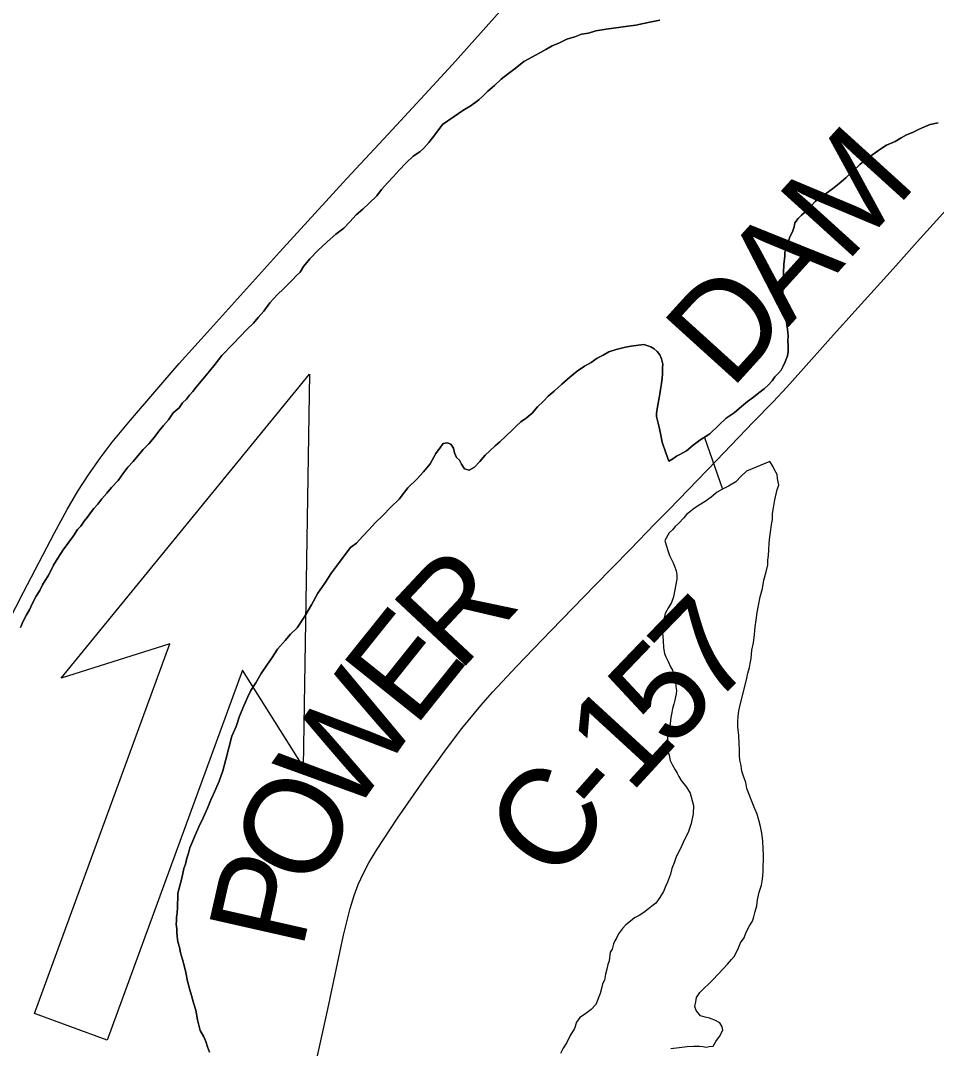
# Model space of a CAD drawing. Extents: x -483 to 680, y 0 to 440.
# Drawn here: x 125.22 to 151.99, y 130.81 to 160.88 of the extents above; entities that cross this region are included whole.
import ezdxf

# ---------------------------------------------------------------- set-up
doc = ezdxf.new("R2010")
doc.units = 0
for name, color, linetype in [('GM_X_County_Road', 7, 'Continuous'), ('GM_X_County_Road_Text', 7, 'Continuous'), ('GM_X_Major_River', 7, 'Continuous'), ('GM_X_Minor_Lake', 7, 'Continuous'), ('GM_X_Minor_River', 7, 'Continuous'), ('GM_X_State_Route', 7, 'Continuous'), ('PM_P_Cells', 7, 'Continuous')]:
    doc.layers.add(name, color=color, linetype=linetype)

msp = doc.modelspace()

# ---------------------------------------------------------------- linework, layer by layer
at = {"layer": 'GM_X_County_Road'}
msp.add_lwpolyline([(133.774, 130.022), (134.2, 131.965), (134.667, 134.122), (134.859, 134.904), (134.973, 135.289), (135.091, 135.606), (135.242, 135.943), (135.401, 136.243), (135.625, 136.613), (136.243, 137.544), (137.021, 138.669), (137.674, 139.576), (138.122, 140.17), (138.674, 140.841), (139.02, 141.238), (139.718, 141.988), (140.735, 143.036), (142.012, 144.352), (143.051, 145.421), (143.762, 146.161), (144.177, 146.579), (145.561, 148.007), (146.64, 149.127), (147.217, 149.729), (147.619, 150.154), (148.032, 150.613), (148.897, 151.586), (149.707, 152.485), (150.726, 153.615), (151.425, 154.404), (152.467, 155.545)], dxfattribs=at)
at = {"layer": 'GM_X_Major_River'}
for points in [[(143.913, 160.893), (143.664, 160.844), (143.434, 160.795), (143.204, 160.746), (142.975, 160.715), (142.764, 160.684), (142.554, 160.653), (142.343, 160.622), (142.037, 160.575), (141.825, 160.506), (141.615, 160.475), (141.422, 160.405), (141.192, 160.337), (140.979, 160.23), (140.766, 160.142), (140.573, 160.034), (140.417, 159.944), (139.933, 159.675), (139.679, 159.474), (139.484, 159.329), (139.269, 159.165), (139.073, 158.981), (138.877, 158.816), (138.739, 158.669), (138.621, 158.558), (138.504, 158.467), (138.368, 158.376), (138.154, 158.25), (137.901, 158.069), (137.551, 157.833), (137.332, 157.536), (137.153, 157.314), (137.015, 157.147), (136.897, 157.037), (136.702, 156.91), (136.486, 156.708), (136.289, 156.505), (136.112, 156.302), (135.954, 156.136), (135.776, 155.933), (135.637, 155.747), (135.401, 155.527), (135.225, 155.361), (135.029, 155.197), (134.851, 154.994), (134.674, 154.809), (134.439, 154.627), (134.185, 154.407), (133.91, 154.15), (133.674, 153.91), (133.495, 153.688)], [(133.495, 153.688), (133.674, 153.91), (133.91, 154.15), (134.185, 154.407), (134.439, 154.627), (134.674, 154.809), (134.851, 154.994), (135.029, 155.197), (135.225, 155.361), (135.401, 155.527), (135.637, 155.747), (135.776, 155.933), (135.954, 156.136), (136.112, 156.302), (136.289, 156.505), (136.486, 156.708), (136.702, 156.91), (136.897, 157.037), (137.015, 157.147), (137.153, 157.314), (137.332, 157.536), (137.551, 157.833), (137.901, 158.069), (138.154, 158.25), (138.368, 158.376), (138.504, 158.467), (138.621, 158.558), (138.739, 158.669), (138.877, 158.816), (139.073, 158.981), (139.269, 159.165), (139.484, 159.329), (139.679, 159.474), (139.933, 159.675), (140.417, 159.944), (140.573, 160.034), (140.766, 160.142), (140.979, 160.23), (141.192, 160.337), (141.422, 160.405), (141.615, 160.475), (141.825, 160.506), (142.037, 160.575), (142.343, 160.622), (142.554, 160.653), (142.764, 160.684), (142.975, 160.715), (143.204, 160.746), (143.434, 160.795), (143.664, 160.844), (143.913, 160.893)], [(147.076, 150.212), (147.194, 150.341), (147.274, 150.452), (147.372, 150.563), (147.452, 150.656), (147.512, 150.768), (147.574, 150.899), (147.636, 151.068), (147.659, 151.2), (147.664, 151.353), (147.651, 151.524), (147.655, 151.657), (147.642, 151.848), (147.578, 152.23), (147.562, 152.326), (147.547, 152.46), (147.533, 152.593), (147.5, 152.766), (147.507, 152.994), (147.513, 153.165), (147.518, 153.317), (147.523, 153.488), (147.532, 153.754), (147.558, 153.981), (147.562, 154.095), (147.605, 154.246), (147.646, 154.359), (147.709, 154.547), (147.79, 154.696), (147.833, 154.847), (147.856, 154.96), (147.955, 155.09), (148.053, 155.182), (148.191, 155.311), (148.329, 155.458), (148.447, 155.587), (148.623, 155.715), (148.778, 155.824), (148.954, 155.951), (149.15, 156.116), (149.345, 156.28), (149.561, 156.482), (149.758, 156.666), (149.934, 156.813), (150.129, 156.958), (150.343, 157.103), (150.537, 157.23), (150.788, 157.336), (150.963, 157.444), (151.118, 157.534), (151.292, 157.604), (151.466, 157.694), (151.64, 157.764), (151.813, 157.834), (152.043, 157.884)], [(152.043, 157.884), (151.813, 157.834), (151.64, 157.764), (151.466, 157.694), (151.292, 157.604), (151.118, 157.534), (150.963, 157.444), (150.788, 157.336), (150.537, 157.23), (150.343, 157.103), (150.129, 156.958), (149.934, 156.813), (149.758, 156.666), (149.561, 156.482), (149.345, 156.28), (149.15, 156.116), (148.954, 155.951), (148.778, 155.824), (148.623, 155.715), (148.447, 155.587), (148.329, 155.458), (148.191, 155.311), (148.053, 155.182), (147.955, 155.09), (147.856, 154.96), (147.833, 154.847), (147.79, 154.696), (147.709, 154.547), (147.646, 154.359), (147.605, 154.246), (147.562, 154.095), (147.558, 153.981), (147.532, 153.754), (147.523, 153.488), (147.518, 153.317), (147.513, 153.165), (147.507, 152.994), (147.5, 152.766), (147.533, 152.593), (147.547, 152.46), (147.562, 152.326), (147.578, 152.23), (147.642, 151.848), (147.655, 151.657), (147.651, 151.524), (147.664, 151.353), (147.659, 151.2), (147.636, 151.068), (147.574, 150.899), (147.512, 150.768), (147.452, 150.656), (147.372, 150.563), (147.274, 150.452), (147.194, 150.341), (147.076, 150.212)], [(133.495, 153.688), (133.395, 153.52), (133.277, 153.41), (133.178, 153.299), (133.06, 153.189), (132.922, 153.041), (132.726, 152.858), (132.509, 152.618), (132.33, 152.376), (132.172, 152.191), (132.033, 152.025), (131.837, 151.841), (131.64, 151.638), (131.423, 151.417), (131.108, 151.085), (130.909, 150.826), (130.75, 150.622), (130.355, 150.159), (130.255, 150.029), (130.157, 149.919), (130.077, 149.807), (129.959, 149.697), (129.859, 149.548), (129.683, 149.402), (129.543, 149.197), (129.405, 149.031), (129.266, 148.864), (129.127, 148.678), (128.969, 148.493), (128.811, 148.327), (128.653, 148.142), (128.514, 147.976), (128.356, 147.81), (128.217, 147.624), (128.077, 147.42), (127.88, 147.217), (127.742, 147.05), (127.603, 146.884), (127.484, 146.736), (127.366, 146.606), (127.266, 146.477), (127.167, 146.347), (127.087, 146.235), (126.987, 146.086), (126.889, 145.995), (126.769, 145.808), (126.63, 145.623), (126.47, 145.4), (126.31, 145.158), (126.189, 144.953), (126.108, 144.784), (126.027, 144.635), (125.947, 144.504), (125.866, 144.374), (125.785, 144.205), (125.684, 144.037), (125.563, 143.813), (125.481, 143.645), (125.4, 143.495), (125.299, 143.308), (125.217, 143.121)], [(125.217, 143.121), (125.299, 143.308), (125.4, 143.495), (125.481, 143.645), (125.563, 143.813), (125.684, 144.037), (125.785, 144.205), (125.866, 144.374), (125.947, 144.504), (126.027, 144.635), (126.108, 144.784), (126.189, 144.953), (126.31, 145.158), (126.47, 145.4), (126.63, 145.623), (126.769, 145.808), (126.889, 145.995), (126.987, 146.086), (127.087, 146.235), (127.167, 146.347), (127.266, 146.477), (127.366, 146.606), (127.484, 146.736), (127.603, 146.884), (127.742, 147.05), (127.88, 147.217), (128.077, 147.42), (128.217, 147.624), (128.356, 147.81), (128.514, 147.976), (128.653, 148.142), (128.811, 148.327), (128.969, 148.493), (129.127, 148.678), (129.266, 148.864), (129.405, 149.031), (129.543, 149.197), (129.683, 149.402), (129.859, 149.548), (129.959, 149.697), (130.077, 149.807), (130.157, 149.919), (130.255, 150.029), (130.355, 150.159), (130.75, 150.622), (130.909, 150.826), (131.108, 151.085), (131.423, 151.417), (131.64, 151.638), (131.837, 151.841), (132.033, 152.025), (132.172, 152.191), (132.33, 152.376), (132.509, 152.618), (132.726, 152.858), (132.922, 153.041), (133.06, 153.189), (133.178, 153.299), (133.277, 153.41), (133.395, 153.52), (133.495, 153.688)], [(133.113, 142.934), (133.31, 143.118), (133.53, 143.453), (133.731, 143.789), (133.913, 144.125), (134.113, 144.423), (134.313, 144.72), (134.512, 144.999), (134.711, 145.259), (134.87, 145.463), (135.045, 145.59), (135.223, 145.793), (135.401, 145.978), (135.598, 146.199), (135.814, 146.401), (136.05, 146.641), (136.286, 146.88), (136.445, 147.084), (136.545, 147.214), (136.819, 147.471), (136.997, 147.675), (137.195, 147.915), (137.357, 148.214), (137.496, 148.4), (137.576, 148.511), (137.691, 148.527), (137.804, 148.485), (137.876, 148.368), (137.91, 148.234), (137.963, 148.099), (138.056, 148.02), (138.109, 147.904), (138.2, 147.768), (138.332, 147.725), (138.487, 147.815), (138.645, 147.981), (138.803, 148.166), (138.94, 148.295), (139.097, 148.442), (139.234, 148.551), (139.588, 148.901), (139.706, 149.011), (139.843, 149.14), (139.999, 149.249), (140.175, 149.395), (140.333, 149.58), (140.51, 149.745), (140.648, 149.893), (140.824, 150.039), (141.04, 150.241), (141.275, 150.443), (141.49, 150.626), (141.704, 150.771), (141.898, 150.878), (142.074, 151.006), (142.248, 151.095), (142.422, 151.184), (142.634, 151.253), (142.903, 151.321), (143.075, 151.353), (143.286, 151.384), (143.438, 151.398), (143.646, 151.334), (143.739, 151.274), (143.832, 151.195), (143.905, 151.097), (143.958, 150.981), (143.992, 150.828), (143.988, 150.733), (143.985, 150.619), (143.982, 150.524), (143.979, 150.429), (143.954, 150.258), (143.93, 150.088), (143.906, 149.956), (143.884, 149.842), (143.86, 149.691), (143.837, 149.578), (143.812, 149.388), (143.809, 149.293), (143.877, 149.025), (143.926, 148.795), (143.976, 148.546), (144.08, 148.238), (144.167, 147.988), (144.284, 148.06), (144.4, 148.132), (144.497, 148.186), (144.691, 148.294), (144.887, 148.458), (145.082, 148.604), (145.373, 148.785), (145.629, 149.042), (145.845, 149.244), (146.079, 149.408), (146.294, 149.591), (146.47, 149.737), (146.646, 149.865), (146.802, 149.993), (146.958, 150.101), (147.076, 150.212)], [(147.076, 150.212), (146.958, 150.101), (146.802, 149.993), (146.646, 149.865), (146.47, 149.737), (146.294, 149.591), (146.079, 149.408), (145.845, 149.244), (145.629, 149.042), (145.373, 148.785), (145.082, 148.604), (144.887, 148.458), (144.691, 148.294), (144.497, 148.186), (144.4, 148.132), (144.284, 148.06), (144.167, 147.988), (144.08, 148.238), (143.976, 148.546), (143.926, 148.795), (143.877, 149.025), (143.809, 149.293), (143.812, 149.388), (143.837, 149.578), (143.86, 149.691), (143.884, 149.842), (143.906, 149.956), (143.93, 150.088), (143.954, 150.258), (143.979, 150.429), (143.982, 150.524), (143.985, 150.619), (143.988, 150.733), (143.992, 150.828), (143.958, 150.981), (143.905, 151.097), (143.832, 151.195), (143.739, 151.274), (143.646, 151.334), (143.438, 151.398), (143.286, 151.384), (143.075, 151.353), (142.903, 151.321), (142.634, 151.253), (142.422, 151.184), (142.248, 151.095), (142.074, 151.006), (141.898, 150.878), (141.704, 150.771), (141.49, 150.626), (141.275, 150.443), (141.04, 150.241), (140.824, 150.039), (140.648, 149.893), (140.51, 149.745), (140.333, 149.58), (140.175, 149.395), (139.999, 149.249), (139.843, 149.14), (139.706, 149.011), (139.588, 148.901), (139.234, 148.551), (139.097, 148.442), (138.94, 148.295), (138.803, 148.166), (138.645, 147.981), (138.487, 147.815), (138.332, 147.725), (138.2, 147.768), (138.109, 147.904), (138.056, 148.02), (137.963, 148.099), (137.91, 148.234), (137.876, 148.368), (137.804, 148.485), (137.691, 148.527), (137.576, 148.511), (137.496, 148.4), (137.357, 148.214), (137.195, 147.915), (136.997, 147.675), (136.819, 147.471), (136.545, 147.214), (136.445, 147.084), (136.286, 146.88), (136.05, 146.641), (135.814, 146.401), (135.598, 146.199), (135.401, 145.978), (135.223, 145.793), (135.045, 145.59), (134.87, 145.463), (134.711, 145.259), (134.512, 144.999), (134.313, 144.72), (134.113, 144.423), (133.913, 144.125), (133.731, 143.789), (133.53, 143.453), (133.31, 143.118), (133.113, 142.934)], [(130.742, 130.706), (130.689, 130.86), (130.637, 131.014), (130.584, 131.149), (130.476, 131.342), (130.391, 131.649), (130.343, 131.936), (130.274, 132.148), (130.223, 132.359), (130.172, 132.532), (130.104, 132.781), (130.054, 133.03), (130.004, 133.241), (129.952, 133.414), (129.901, 133.606), (129.869, 133.778), (129.817, 133.932), (129.802, 134.085), (129.788, 134.219), (129.791, 134.313), (129.776, 134.447), (129.779, 134.542), (129.783, 134.656), (129.805, 134.77), (129.811, 134.941), (129.814, 135.055), (129.819, 135.188), (129.824, 135.359), (129.933, 135.792), (129.977, 135.981), (129.999, 136.076), (130.042, 136.207), (130.085, 136.377), (130.128, 136.528), (130.171, 136.679), (130.254, 136.885), (130.336, 137.073), (130.438, 137.297), (130.561, 137.56), (130.684, 137.841), (130.787, 138.085), (130.849, 138.235), (130.931, 138.403), (131.033, 138.628), (131.138, 138.929), (131.225, 139.269), (131.312, 139.608), (131.399, 139.948), (131.522, 140.229), (131.627, 140.53), (131.751, 140.83), (131.854, 141.074), (131.956, 141.28), (132.096, 141.503), (132.258, 141.783), (132.418, 142.025), (132.577, 142.248), (132.737, 142.49), (132.955, 142.749), (133.113, 142.934)], [(133.113, 142.934), (132.955, 142.749), (132.737, 142.49), (132.577, 142.248), (132.418, 142.025), (132.258, 141.783), (132.096, 141.503), (131.956, 141.28), (131.854, 141.074), (131.751, 140.83), (131.627, 140.53), (131.522, 140.229), (131.399, 139.948), (131.312, 139.608), (131.225, 139.269), (131.138, 138.929), (131.033, 138.628), (130.931, 138.403), (130.849, 138.235), (130.787, 138.085), (130.684, 137.841), (130.561, 137.56), (130.438, 137.297), (130.336, 137.073), (130.254, 136.885), (130.171, 136.679), (130.128, 136.528), (130.085, 136.377), (130.042, 136.207), (129.999, 136.076), (129.977, 135.981), (129.933, 135.792), (129.824, 135.359), (129.819, 135.188), (129.814, 135.055), (129.811, 134.941), (129.805, 134.77), (129.783, 134.656), (129.779, 134.542), (129.776, 134.447), (129.791, 134.313), (129.788, 134.219), (129.802, 134.085), (129.817, 133.932), (129.869, 133.778), (129.901, 133.606), (129.952, 133.414), (130.004, 133.241), (130.054, 133.03), (130.104, 132.781), (130.172, 132.532), (130.223, 132.359), (130.274, 132.148), (130.343, 131.936), (130.391, 131.649), (130.476, 131.342), (130.584, 131.149), (130.637, 131.014), (130.689, 130.86), (130.742, 130.706)]]:
    msp.add_lwpolyline(points, dxfattribs=at)
at = {"layer": 'GM_X_Minor_Lake'}
for points in [[(147.12, 147.984), (146.444, 147.702), (146.287, 147.555), (146.13, 147.389), (145.916, 147.263), (145.742, 147.174), (145.587, 147.084), (145.411, 146.938), (145.235, 146.81), (145.06, 146.702), (144.924, 146.611), (144.827, 146.538), (144.69, 146.429), (144.611, 146.336), (144.453, 146.17), (144.355, 146.079), (144.276, 145.986), (144.178, 145.894), (144.056, 145.67), (144.09, 145.536), (144.142, 145.382), (144.194, 145.228), (144.248, 145.112), (144.302, 145.015), (144.337, 144.919), (144.39, 144.784), (144.405, 144.669), (144.401, 144.536), (144.308, 144.026), (144.246, 143.857), (144.165, 143.707), (144.064, 143.539), (144.02, 143.332), (143.995, 143.161), (143.989, 142.971), (144.001, 142.743), (144.013, 142.533), (144.046, 142.361), (144.081, 142.264), (144.152, 142.129), (144.224, 141.974), (144.278, 141.877), (144.294, 141.782), (144.328, 141.666), (144.362, 141.532), (144.377, 141.398), (144.392, 141.284), (144.389, 141.189), (144.367, 141.095), (144.345, 141), (144.322, 140.887), (144.28, 140.755), (144.257, 140.642), (144.233, 140.49), (144.209, 140.32), (144.184, 140.13), (144.141, 139.98), (144.137, 139.866), (144.134, 139.771), (144.129, 139.6), (144.145, 139.504), (144.179, 139.389), (144.212, 139.236), (144.266, 139.12), (144.356, 138.964), (144.41, 138.867), (144.464, 138.771), (144.536, 138.654), (144.609, 138.557), (144.683, 138.459), (144.791, 138.284), (144.894, 137.919), (144.886, 137.672), (144.82, 137.389), (144.735, 137.126), (144.633, 136.92), (144.552, 136.751), (144.47, 136.583), (144.389, 136.414), (144.326, 136.245), (144.263, 136.076), (144.22, 135.906), (144.137, 135.681), (144.075, 135.55), (144.013, 135.4), (143.913, 135.232), (143.793, 135.065), (143.676, 134.973), (143.578, 134.901), (143.442, 134.791), (143.305, 134.7), (143.17, 134.629), (143.053, 134.538), (142.916, 134.428), (142.817, 134.317), (142.698, 134.169), (142.656, 134.056), (142.596, 133.963)], [(147.12, 147.984), (146.444, 147.702), (146.287, 147.555), (146.13, 147.389), (145.916, 147.263), (145.742, 147.174), (145.587, 147.084), (145.411, 146.938), (145.235, 146.81), (145.06, 146.702), (144.924, 146.611), (144.827, 146.538), (144.69, 146.429), (144.611, 146.336), (144.453, 146.17), (144.355, 146.079), (144.276, 145.986), (144.178, 145.894), (144.056, 145.67), (144.09, 145.536), (144.142, 145.382), (144.194, 145.228), (144.248, 145.112), (144.302, 145.015), (144.337, 144.919), (144.39, 144.784), (144.405, 144.669), (144.401, 144.536), (144.308, 144.026), (144.246, 143.857), (144.165, 143.707), (144.064, 143.539), (144.02, 143.332), (143.995, 143.161), (143.989, 142.971), (144.001, 142.743), (144.013, 142.533), (144.046, 142.361), (144.081, 142.264), (144.152, 142.129), (144.224, 141.974), (144.278, 141.877), (144.294, 141.782), (144.328, 141.666), (144.362, 141.532), (144.377, 141.398), (144.392, 141.284), (144.389, 141.189), (144.367, 141.095), (144.345, 141), (144.322, 140.887), (144.28, 140.755), (144.257, 140.642), (144.233, 140.49), (144.209, 140.32), (144.184, 140.13), (144.141, 139.98), (144.137, 139.866), (144.134, 139.771), (144.129, 139.6), (144.145, 139.504), (144.179, 139.389), (144.212, 139.236), (144.266, 139.12), (144.356, 138.964), (144.41, 138.867), (144.464, 138.771), (144.536, 138.654), (144.609, 138.557), (144.683, 138.459), (144.791, 138.284), (144.894, 137.919), (144.886, 137.672), (144.82, 137.389), (144.735, 137.126), (144.633, 136.92), (144.552, 136.751), (144.47, 136.583), (144.389, 136.414), (144.326, 136.245), (144.263, 136.076), (144.22, 135.906), (144.137, 135.681), (144.075, 135.55), (144.013, 135.4), (143.913, 135.232), (143.793, 135.065), (143.676, 134.973), (143.578, 134.901), (143.442, 134.791), (143.305, 134.7), (143.17, 134.629), (143.053, 134.538), (142.916, 134.428), (142.817, 134.317), (142.698, 134.169), (142.656, 134.056), (142.596, 133.963)], [(145.361, 131.703), (145.229, 131.726), (145.097, 131.769), (144.968, 131.925), (144.934, 132.04), (144.957, 132.173), (144.981, 132.305), (145.081, 132.454), (145.454, 132.822), (145.612, 132.988), (145.77, 133.154), (145.888, 133.283), (146.006, 133.412), (146.085, 133.505), (146.187, 133.711), (146.269, 133.898), (146.369, 134.047), (146.432, 134.216), (146.533, 134.403), (146.613, 134.533), (146.656, 134.665), (146.699, 134.816), (146.742, 134.986), (146.767, 135.156), (146.812, 135.383), (146.876, 135.59), (146.898, 135.703), (146.922, 135.855), (146.927, 135.988), (146.932, 136.159), (146.937, 136.311), (146.942, 136.463), (146.929, 136.653), (146.917, 136.882), (146.886, 137.111), (146.854, 137.303), (146.803, 137.494), (146.752, 137.667), (146.681, 137.822), (146.611, 138.015), (146.54, 138.188), (146.452, 138.419), (146.42, 138.592), (146.367, 138.745), (146.315, 138.899), (146.299, 138.995), (146.283, 139.091), (146.25, 139.244), (146.236, 139.396), (146.241, 139.549), (146.228, 139.739), (146.216, 139.968), (146.186, 140.216), (146.191, 140.368), (146.196, 140.52), (146.22, 140.691), (146.265, 140.898), (146.44, 141.596), (146.484, 141.785), (146.527, 141.955), (146.55, 142.068), (146.574, 142.22), (146.601, 142.466), (146.645, 142.674), (146.672, 142.92), (146.699, 143.147), (146.724, 143.337), (146.75, 143.564), (146.795, 143.772), (146.841, 144.018), (146.906, 144.263), (146.952, 144.509), (147.017, 144.754), (147.061, 144.961), (147.066, 145.095), (147.089, 145.227), (147.094, 145.398), (147.101, 145.588), (147.126, 145.777), (147.151, 145.986), (147.175, 146.137), (147.199, 146.288), (147.204, 146.46), (147.229, 146.63), (147.274, 146.857), (147.341, 147.159), (147.383, 147.29), (147.351, 147.482), (147.336, 147.596), (147.246, 147.752), (147.211, 147.848), (147.12, 147.984)], [(145.361, 131.703), (145.229, 131.726), (145.097, 131.769), (144.968, 131.925), (144.934, 132.04), (144.957, 132.173), (144.981, 132.305), (145.081, 132.454), (145.454, 132.822), (145.612, 132.988), (145.77, 133.154), (145.888, 133.283), (146.006, 133.412), (146.085, 133.505), (146.187, 133.711), (146.269, 133.898), (146.369, 134.047), (146.432, 134.216), (146.533, 134.403), (146.613, 134.533), (146.656, 134.665), (146.699, 134.816), (146.742, 134.986), (146.767, 135.156), (146.812, 135.383), (146.876, 135.59), (146.898, 135.703), (146.922, 135.855), (146.927, 135.988), (146.932, 136.159), (146.937, 136.311), (146.942, 136.463), (146.929, 136.653), (146.917, 136.882), (146.886, 137.111), (146.854, 137.303), (146.803, 137.494), (146.752, 137.667), (146.681, 137.822), (146.611, 138.015), (146.54, 138.188), (146.452, 138.419), (146.42, 138.592), (146.367, 138.745), (146.315, 138.899), (146.299, 138.995), (146.283, 139.091), (146.25, 139.244), (146.236, 139.396), (146.241, 139.549), (146.228, 139.739), (146.216, 139.968), (146.186, 140.216), (146.191, 140.368), (146.196, 140.52), (146.22, 140.691), (146.265, 140.898), (146.44, 141.596), (146.484, 141.785), (146.527, 141.955), (146.55, 142.068), (146.574, 142.22), (146.601, 142.466), (146.645, 142.674), (146.672, 142.92), (146.699, 143.147), (146.724, 143.337), (146.75, 143.564), (146.795, 143.772), (146.841, 144.018), (146.906, 144.263), (146.952, 144.509), (147.017, 144.754), (147.061, 144.961), (147.066, 145.095), (147.089, 145.227), (147.094, 145.398), (147.101, 145.588), (147.126, 145.777), (147.151, 145.986), (147.175, 146.137), (147.199, 146.288), (147.204, 146.46), (147.229, 146.63), (147.274, 146.857), (147.341, 147.159), (147.383, 147.29), (147.351, 147.482), (147.336, 147.596), (147.246, 147.752), (147.211, 147.848), (147.12, 147.984)], [(142.596, 133.963), (142.555, 133.869), (142.512, 133.719), (142.452, 133.626), (142.425, 133.379), (142.384, 133.266), (142.36, 133.134), (142.317, 132.983), (142.293, 132.813), (142.232, 132.701), (142.21, 132.606), (142.166, 132.418), (142.042, 132.098), (141.903, 131.951), (141.708, 131.805), (141.572, 131.715), (141.473, 131.585), (141.41, 131.397), (141.289, 131.191), (141.187, 130.986), (141.086, 130.818), (141.006, 130.668)], [(142.596, 133.963), (142.555, 133.869), (142.512, 133.719), (142.452, 133.626), (142.425, 133.379), (142.384, 133.266), (142.36, 133.134), (142.317, 132.983), (142.293, 132.813), (142.232, 132.701), (142.21, 132.606), (142.166, 132.418), (142.042, 132.098), (141.903, 131.951), (141.708, 131.805), (141.572, 131.715), (141.473, 131.585), (141.41, 131.397), (141.289, 131.191), (141.187, 130.986), (141.086, 130.818), (141.006, 130.668)], [(144.228, 130.808), (144.477, 130.838), (144.706, 130.869), (144.897, 130.881), (145.068, 130.876), (145.163, 130.872), (145.258, 130.85), (145.354, 130.866), (145.468, 130.881), (145.549, 131.012), (145.649, 131.161), (145.75, 131.347), (145.734, 131.443), (145.661, 131.56), (145.512, 131.641), (145.361, 131.703)], [(144.228, 130.808), (144.477, 130.838), (144.706, 130.869), (144.897, 130.881), (145.068, 130.876), (145.163, 130.872), (145.258, 130.85), (145.354, 130.866), (145.468, 130.881), (145.549, 131.012), (145.649, 131.161), (145.75, 131.347), (145.734, 131.443), (145.661, 131.56), (145.512, 131.641), (145.361, 131.703)]]:
    msp.add_lwpolyline(points, dxfattribs=at)
at = {"layer": 'GM_X_Minor_River'}
msp.add_line((145.218, 148.682), (145.742, 147.174), dxfattribs=at)
at = {"layer": 'GM_X_State_Route'}
msp.add_lwpolyline([(124.201, 142.001), (125.311, 144.157), (126.213, 145.896), (126.583, 146.581), (126.902, 147.117), (127.206, 147.589), (127.546, 148.074), (127.904, 148.546), (128.439, 149.194), (129.862, 150.842), (130.772, 151.864), (132.792, 154.103), (134.762, 156.262), (135.971, 157.557), (136.919, 158.586), (137.848, 159.588), (139.558, 161.519)], dxfattribs=at)
at = {"layer": 'PM_P_Cells'}
for p, q in [((126.413, 141.644), (133.669, 150.532)), ((133.669, 150.532), (133.482, 139.06)), ((125.631, 131.832), (129.585, 142.648)), ((129.585, 142.648), (126.413, 141.644)), ((131.706, 141.873), (127.752, 131.057)), ((133.482, 139.06), (131.706, 141.873)), ((127.752, 131.057), (125.631, 131.832))]:
    msp.add_line(p, q, dxfattribs=at)

# ---------------------------------------------------------------- texts
at = {"layer": 'GM_X_County_Road_Text'}
for s, rotation, p in [('M', 47.7475, (149.339, 153.753)), ('A', 47.804, (147.66, 151.902)), ('D', 47.801, (145.981, 150.05)), ('R', 46.9046, (138.022, 141.781)), ('7', 45.8611, (145.424, 140.769)), ('E', 51.3067, (136.731, 140.166)), ('5', 46.2015, (144.216, 139.509)), ('W', 54.9439, (134.869, 137.51)), ('1', 47.4202, (143.043, 138.232)), ('C', 51.598, (140.858, 135.57)), ('-', 48.6121, (142.282, 137.368)), ('O', 63.7363, (133.822, 135.367)), ('P', 77.2344, (133.457, 133.664))]:
    msp.add_text(s, height=2.841, rotation=rotation, dxfattribs=at).set_placement(p)

doc.saveas('drawing.dxf')
